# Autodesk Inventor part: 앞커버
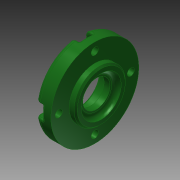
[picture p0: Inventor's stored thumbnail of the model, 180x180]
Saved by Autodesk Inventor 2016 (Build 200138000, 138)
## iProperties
Created: 2015-11
Part Number: 앞커버
Material: 알루미늄 6061
Document SubType Name: Modeling
Designer: mduedu
Density: 1 g/cm^3
Appearance: 매끄러움 - 짙은 산림 녹색
Author: mduedu
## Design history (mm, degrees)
sketch "스케치1"
  geometry: L1 (-7, 0)-(7, 0); L2 (-7, 0)-(-7, 27.5); L3 (-7, 27.5)-(3, 27.5); L4 (3, 27.5)-(3, 16); L5 (3, 16)-(7, 16); L6 (7, 16)-(7, 0); 2 further points
  constraints: 12 end point, 3 perpendicular, 2 parallel, 1 coincident, 1 horizontal, 1 midpoint
  dimensions: "d0" = 14 distance of L1.start L1.end; "d1" = 55 diameter of L3 L1; "d2" = 4 distance of L4.end L5.end; "d3" = 32 diameter of L5 L1
revolve "회전1" sketch "스케치1" stored, may be unused: angle "d4" = 90 deg
hole "구멍1" diameter "d7" = 25; stored, may be unused: countersink angle "d11" = 90 deg, drill point angle "d13" = 0 deg; dims "d5" = 10, "d6" = 10, "d8" = 6, "d9" = 4, "d10" = 2, "d12" = 3
hole "구멍2" diameter "d16" = 25; stored, may be unused: countersink angle "d20" = 90 deg, drill point angle "d22" = 0 deg; dims "d17" = 6, "d18" = 4, "d19" = 2, "d21" = 7.3, "d61" = 10, "d62" = 10
hole "구멍3" diameter "d25" = 17; stored, may be unused: countersink angle "d29" = 90 deg, drill point angle "d31" = 0 deg; dims "d23" = 10, "d24" = 10, "d26" = 6, "d27" = 4, "d28" = 2, "d30" = 4.2
chamfer "모따기1" distance "d32" = 0.7; stored, may be unused: second distance "d33" = 2, angle "d34" = 30 deg
fillet "모깎기1" dims "d35" = 0.3
fillet "모깎기2" dims "d36" = 3
fillet "모깎기3" dims "d37" = 3
sketch "스케치2" dims "d39" = 45
  geometry: C1 r 12.904 at (0, 0) reference; C2 r 24.5 at (0, 0) reference; 6 further points
  constraints: 2 vertical alignment, 1 coincident, 7 other
  dimensions: "d42" = 360 deg dimension on point (0, 0) point (0, 22.5) (derived)
sketch "스케치3"
  geometry: 8 further points
  constraints: 4 coincident
hole "구멍4" sketch "스케치3" at (-22.5, 0), (0, -22.5), (22.5, 0), (0, 22.5) diameter "d44" = 4.5; stored, may be unused: countersink angle "d48" = 90 deg, drill point angle "d50" = 0 deg; dims "d45" = 6, "d46" = 8, "d47" = 4.6, "d49" = 8
sketch "스케치4"
  geometry: L1 (-4, 0)-(-4, -4.708); L2 (4, 0)-(4, -4.708); A1 r 4 centre (0, 0) between (-4, 0) and (4, 0) reference; A2 r 27.5 centre (0, 22.5) between (-4, -4.708) and (4, -4.708) reference; 3 further points
  constraints: 4 end point, 4 point on circle, 2 tangent, 1 parallel, 1 vertical
extrude "돌출1" cut sketch "스케치4" stored distance "d51" = 0; taper "d52" = 0 deg
fillet "모깎기5" dims "d56" = 0.3
fillet "모깎기6" dims "d57" = 1
chamfer "모따기2" distance "d63" = 1; stored, may be unused: second distance "d64" = 2, angle "d65" = 45 deg
node "솔리드1"
pattern_circular "원형 패턴1" dims angle "d54" = 360 deg
